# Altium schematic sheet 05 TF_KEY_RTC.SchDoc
size 386 x 246 mm
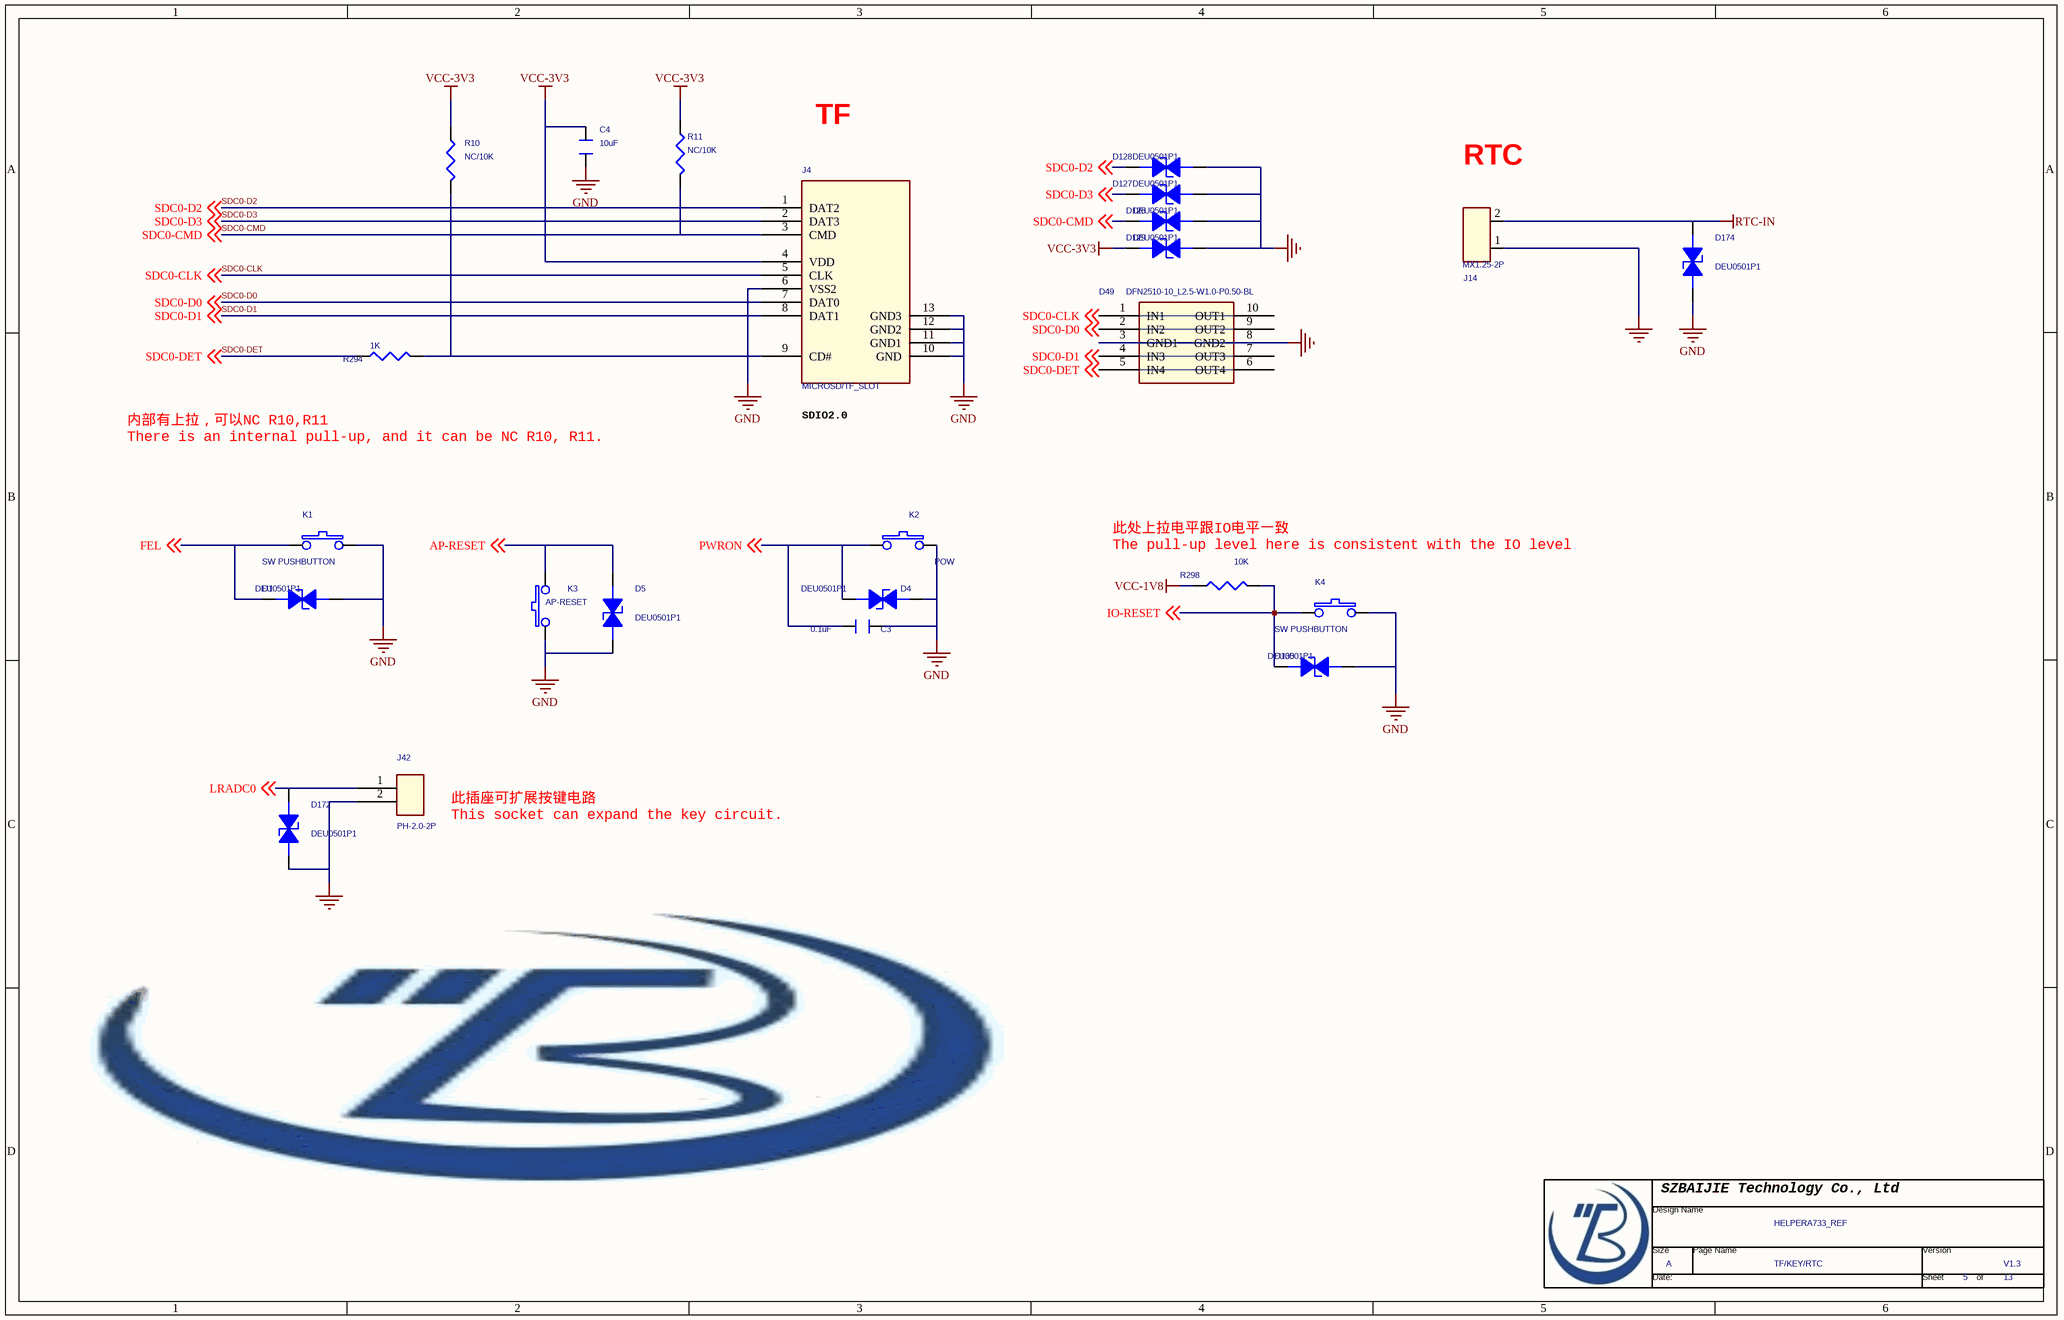
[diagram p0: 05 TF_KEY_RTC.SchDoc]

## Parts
*  Page Count: 13  Page Number: 5  Page Size: A  Title: HELPERA733_REF  RevCode: V1.3  Doc: TF/KEY/RTC  (hidden comment: TitleBlock0-BJ)  (graphical)
C3  0.1uF  [C0402]
C4  10uF  [C0603]
D1  DEU0501P1  [ESD0402]
D4  DEU0501P1  [ESD0402]
D5  DEU0501P1  [ESD0402]
D49  DFN2510-10_L2.5-W1.0-P0.50-BL  [RCLAMP0524P]
D126  DEU0501P1  [ESD0402]
D127  DEU0501P1  [ESD0402]
D128  DEU0501P1  [ESD0402]
D129  DEU0501P1  [ESD0402]
D130  DEU0501P1  [ESD0402]
D172  DEU0501P1  [ESD0402]
D174  DEU0501P1  [ESD0402]
J4  MICROSD/TF_SLOT  [tf_push1]
J14  MX1.25-2P  [MX1.25-2P]
J42  PH-2.0-2P  [PH-2.0-2P]
K1  SW PUSHBUTTON  [KEY_3X4]
K2  POW  [KEY_3X4]
K3  AP-RESET  [KEY_3X4]
K4  SW PUSHBUTTON  [KEY_3X4]
R10  NC/10K  [R0402]
R11  NC/10K  [R0402]
R294  1K  [R0402]
R298  10K  [R0402]

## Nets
GND: C3.2 C4.1 D1.2(CATHODE) D4.1(ANODE) D5.1(ANODE) D49.3(GND1) D49.8(GND2) D126.1(ANODE) D127.1(ANODE) D128.1(ANODE) D129.1(ANODE) D130.2(CATHODE) D172.1(ANODE) D174.1(ANODE) J4.6(VSS2) J4.10(GND) J4.11(GND1) J4.12(GND2) J4.13(GND3) J14.1 J42.2 K1.2 K2.1 K3.1 K4.2
RTC-IN: D174.2(CATHODE) J14.2
VCC-1V8: R298.1
VCC-3V3: C4.2 D129.2(CATHODE) J4.4(VDD) R10.1 R11.1
AP-RESET: D5.2(CATHODE) K3.2 ; off-sheet AP-RESET
FEL: D1.1(ANODE) K1.1 ; off-sheet FEL
IO-RESET: D130.1(ANODE) K4.1 R298.2 ; off-sheet IO-RESET
LRADC0: D172.2(CATHODE) J42.1 ; off-sheet LRADC0
PWRON: C3.1 D4.2(CATHODE) K2.2 ; off-sheet PWRON
SDC0-CLK: D49.1(IN1) D49.10(OUT1) J4.5(CLK) ; off-sheet SDC0-CLK
SDC0-CMD: D126.2(CATHODE) J4.3(CMD) R11.2 ; off-sheet SDC0-CMD
SDC0-D0: D49.2(IN2) D49.9(OUT2) J4.7(DAT0) ; off-sheet SDC0-D0
SDC0-D1: D49.4(IN3) D49.7(OUT3) J4.8(DAT1) ; off-sheet SDC0-D1
SDC0-D2: D128.2(CATHODE) J4.1(DAT2) ; off-sheet SDC0-D2
SDC0-D3: D127.2(CATHODE) J4.2(DAT3) ; off-sheet SDC0-D3
SDC0-DET: D49.5(IN4) D49.6(OUT4) R294.1 ; off-sheet SDC0-DET
NetJ4_9: J4.9(CD#) R10.2 R294.2

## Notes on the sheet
- TF
- (near J14) RTC
- 内部有上拉，可以NC R10,R11
  There is an internal pull-up, and it can be NC R10, R11.
- SDIO2.0
- (near R298) 此处上拉电平跟IO电平一致
  The pull-up level here is consistent with the IO level
- 此插座可扩展按键电路
  This socket can expand the key circuit.

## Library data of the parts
C3 = CAPACITOR_0_Dup1
C4 = CAPACITOR_0_Dup1: PAGE: 2
D1 D4 D5 D126-D130 D172 D174 = 1_1.5KE100A_Dup1: 1ST PART DESCRIPTION: WILL ESD9B5V Bidirection ESD Protection
D49 = rRClamp0524P
J4 = SDMMC SLOT_0
J14 = CON6_0: CON;HDR,6PX1,1MM,R/A,H1.9,SMT; VENDER P/N: 3800-6; VENDER: E&T; P/N: XXXXXXXXXXXX; device: CONN_ENT3800_6_1
J42 = CON2
K2 K3 = SW PUSHBUTTON
R10 R11 R294 = R_Dup5
R298 = R_Dup2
